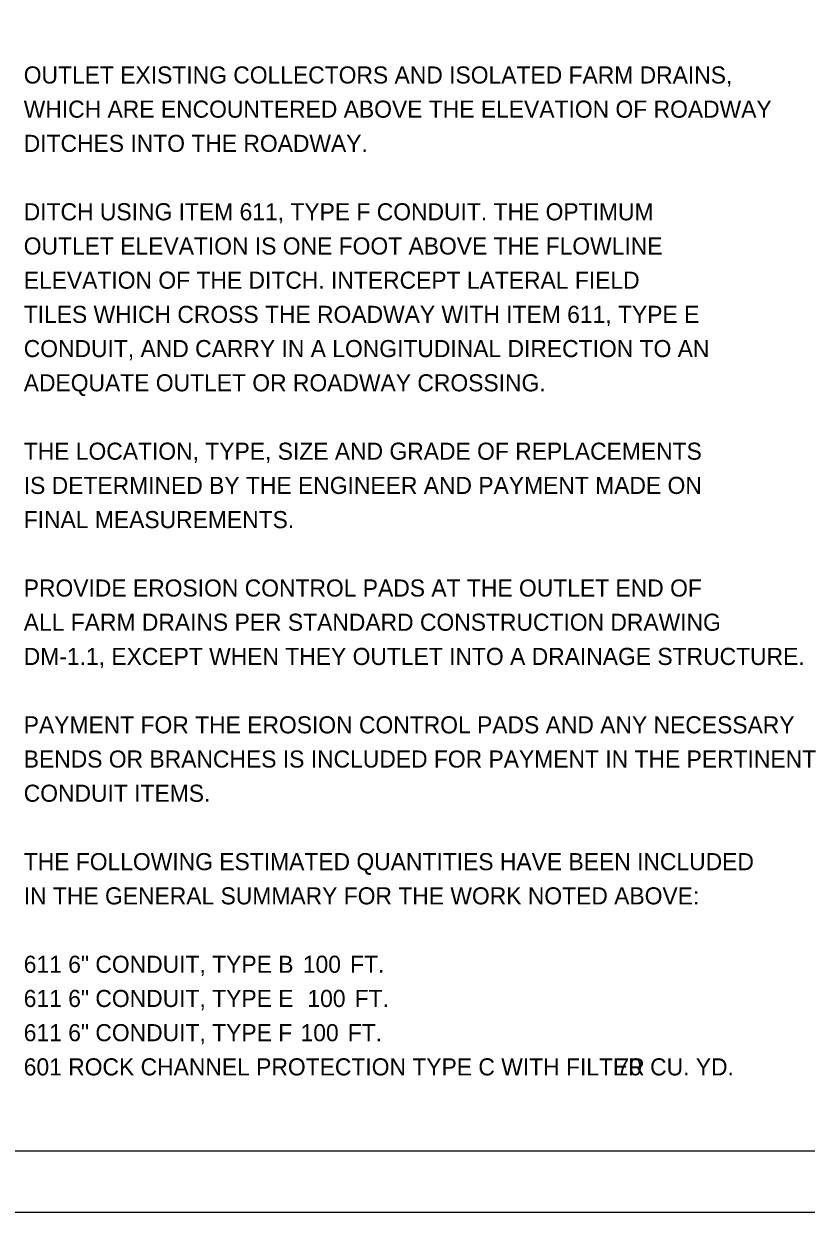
# Model space of a CAD drawing. Extents: x 0 to 37.9, y 0 to 22.
# Drawn here: x 24.66 to 31.07, y 0 to 9.73 of the extents above; entities that cross this region are included whole.
import ezdxf

# ---------------------------------------------------------------- set-up
doc = ezdxf.new("R2010")
doc.units = 0
for name, color, linetype in [('SH_Border', 7, 'Continuous'), ('SH_Cut_Line', 7, 'Continuous'), ('SH_Text', 7, 'Continuous')]:
    doc.layers.add(name, color=color, linetype=linetype)

msp = doc.modelspace()

# ---------------------------------------------------------------- linework, layer by layer
at = {"layer": 'SH_Border'}
msp.add_lwpolyline([(1.5, 21.5), (33.5, 21.5), (33.5, 0.5), (1.5, 0.5)], close=True, dxfattribs=at)
at = {"layer": 'SH_Cut_Line'}
msp.add_lwpolyline([(0, 0), (34, 0), (34, 22), (0, 22)], close=True, dxfattribs=at)

# ---------------------------------------------------------------- texts
at = {"layer": 'SH_Text'}
for s, p in [('OUTLET EXISTING COLLECTORS AND ISOLATED FARM DRAINS,', (24.66, 9.24)), ('WHICH ARE ENCOUNTERED ABOVE THE ELEVATION OF ROADWAY', (24.66, 8.96)), ('DITCHES INTO THE ROADWAY.', (24.66, 8.68)), ('DITCH USING ITEM 611, TYPE F CONDUIT. THE OPTIMUM', (24.66, 8.12)), ('OUTLET ELEVATION IS ONE FOOT ABOVE THE FLOWLINE', (24.66, 7.84)), ('ELEVATION OF THE DITCH. INTERCEPT LATERAL FIELD', (24.66, 7.56)), ('TILES WHICH CROSS THE ROADWAY WITH ITEM 611, TYPE E', (24.66, 7.28)), ('CONDUIT, AND CARRY IN A LONGITUDINAL DIRECTION TO AN', (24.66, 7)), ('ADEQUATE OUTLET OR ROADWAY CROSSING.', (24.66, 6.72)), ('THE LOCATION, TYPE, SIZE AND GRADE OF REPLACEMENTS', (24.66, 6.16)), ('IS DETERMINED BY THE ENGINEER AND PAYMENT MADE ON', (24.66, 5.88)), ('FINAL MEASUREMENTS.', (24.66, 5.6)), ('PROVIDE EROSION CONTROL PADS AT THE OUTLET END OF', (24.66, 5.04)), ('ALL FARM DRAINS PER STANDARD CONSTRUCTION DRAWING', (24.66, 4.76)), ('DM-1.1, EXCEPT WHEN THEY OUTLET INTO A DRAINAGE STRUCTURE.', (24.66, 4.48)), ('PAYMENT FOR THE EROSION CONTROL PADS AND ANY NECESSARY', (24.66, 3.92)), ('BENDS OR BRANCHES IS INCLUDED FOR PAYMENT IN THE PERTINENT', (24.66, 3.64)), ('CONDUIT ITEMS.', (24.66, 3.36)), ('THE FOLLOWING ESTIMATED QUANTITIES HAVE BEEN INCLUDED', (24.66, 2.8)), ('IN THE GENERAL SUMMARY FOR THE WORK NOTED ABOVE:', (24.66, 2.52)), ('611 6" CONDUIT, TYPE B  ', (24.66, 1.96)), ('100', (26.9463, 1.96)), (' FT.', (27.2815, 1.96)), ('611 6" CONDUIT, TYPE E   ', (24.66, 1.68)), ('100', (26.9837, 1.68)), (' FT.', (27.3189, 1.68)), ('611 6" CONDUIT, TYPE F  ', (24.66, 1.4)), ('100', (26.9276, 1.4)), (' FT.', (27.2628, 1.4)), ('601 ROCK CHANNEL PROTECTION TYPE C WITH FILTER ', (24.66, 1.12)), ('70', (29.5154, 1.12)), (' CU. YD.', (29.7389, 1.12))]:
    msp.add_text(s, height=0.14, dxfattribs=at).set_placement(p)

doc.saveas('drawing.dxf')
